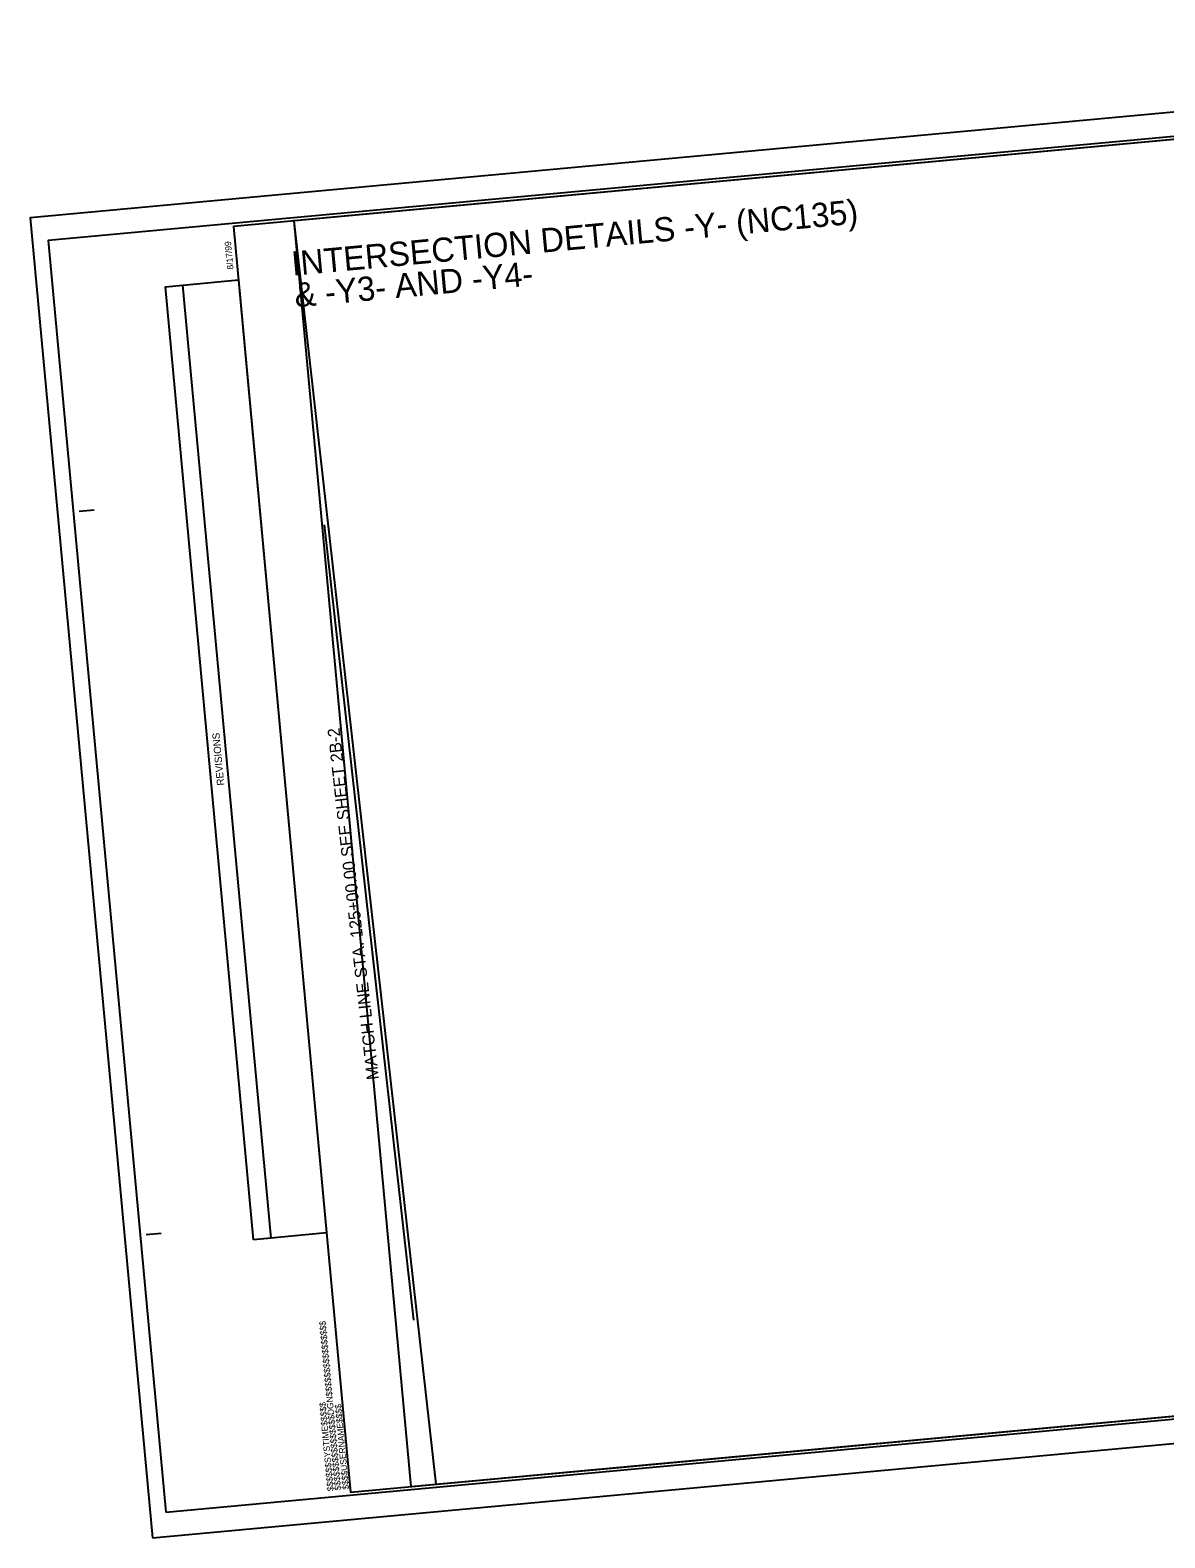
# Model space of a CAD drawing. Extents: x 1724152 to 1726026, y 971581 to 972827.
# Drawn here: x 1724152 to 1725089, y 971581 to 972827 of the extents above; entities that cross this region are included whole.
import ezdxf

# ---------------------------------------------------------------- set-up
doc = ezdxf.new("R2010")
doc.units = 0
for name, color, linetype in [('Matchline', 7, 'Continuous'), ('Matchline Text', 7, 'Continuous'), ('Prop Dimension', 7, 'Continuous'), ('Sheet Block Revision CELL', 7, 'Continuous'), ('Sheet Clip Boundary CELL', 7, 'Continuous'), ('Sheet Layout Plan Border', 7, 'Continuous'), ('Sheet Plan CELL', 7, 'Continuous'), ('Sheet Plot Border Inside CELL', 7, 'Continuous'), ('Sheet Plot Border Outside CELL', 7, 'Continuous')]:
    doc.layers.add(name, color=color, linetype=linetype)

msp = doc.modelspace()

# ---------------------------------------------------------------- linework, layer by layer
at = {"layer": 'Matchline'}
msp.add_line((1724469, 971760.9), (1724395.1, 972418.1), dxfattribs=at)
at = {"layer": 'Sheet Block Revision CELL'}
msp.add_line((1724351.1, 971828.8), (1724278.3, 972616), dxfattribs=at)
msp.add_lwpolyline([(1724336.6, 971827.4), (1724263.8, 972614.7), (1724324.1, 972620.3), (1724396.9, 971833)], close=True, dxfattribs=at)
at = {"layer": 'Sheet Clip Boundary CELL'}
msp.add_lwpolyline([(1724466.5, 971623.5), (1725860.6, 971752.5), (1725783.3, 972587.5), (1725594.9, 972570), (1725575.4, 972780.6), (1724369.8, 972669.1)], close=True, dxfattribs=at)
at = {"layer": 'Sheet Layout Plan Border'}
msp.add_lwpolyline([(1725733.8, 972795.3), (1725723.9, 972794.3), (1724369.8, 972669.1), (1724487, 971625.4), (1724638.1, 971639.4), (1724679.6, 971643.2), (1725830.7, 971749.7)], close=True, dxfattribs=at)
at = {"layer": 'Sheet Plan CELL'}
for p, q in [((1724320, 972664.5), (1724320, 972664.5)), ((1724192.6, 972429.2), (1724205.1, 972430.4)), ((1724247.9, 971831.8), (1724260.4, 971832.9)), ((1724416.7, 971618.9), (1724416.7, 971618.9))]:
    msp.add_line(p, q, dxfattribs=at)
msp.add_lwpolyline([(1725813.6, 972802.7), (1724320, 972664.5), (1724416.7, 971618.9), (1725910.4, 971757.1)], close=True, dxfattribs=at)
at = {"layer": 'Sheet Plot Border Inside CELL'}
msp.add_lwpolyline([(1724264.1, 971602.3), (1725923, 971755.8), (1725825.8, 972806.3), (1724166.9, 972652.8)], close=True, dxfattribs=at)
at = {"layer": 'Sheet Plot Border Outside CELL'}
msp.add_lwpolyline([(1724253, 971581.2), (1725929.4, 971736.3), (1725828.5, 972826.6), (1724152.1, 972671.5)], close=True, dxfattribs=at)

# ---------------------------------------------------------------- texts
at = {"layer": 'Matchline Text'}
msp.add_text('MATCH LINE STA. 125+00.00 SEE SHEET 2B-2', height=10, rotation=96.4179, dxfattribs=at).set_placement((1724440.1, 971960.1))
at = {"layer": 'Prop Dimension'}
for s, p in [('INTERSECTION DETAILS -Y- (NC135)', (1724368.8, 972623.7)), ('& -Y3- AND -Y4-', (1724371.2, 972597.6))]:
    msp.add_text(s, height=20, rotation=5.2862, dxfattribs=at).set_placement(p)
at = {"layer": 'Sheet Block Revision CELL'}
msp.add_text('REVISIONS', height=6, rotation=95.2862, dxfattribs=at).set_placement((1724312.4, 972202.9))
at = {"layer": 'Sheet Plan CELL'}
for s, p in [('8/17/99', (1724320, 972629.1)), ('$$$$$$$$$$$$$$$$DGN$$$$$$$$$$$$$$$$', (1724408.9, 971620.6)), ('$$$$$$SYSTIME$$$$$', (1724402.8, 971620)), ('$$$$USERNAME$$$$', (1724415.4, 971621.2))]:
    msp.add_text(s, height=5.25, rotation=95.2862, dxfattribs=at).set_placement(p)

doc.saveas('drawing.dxf')
